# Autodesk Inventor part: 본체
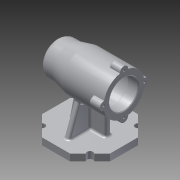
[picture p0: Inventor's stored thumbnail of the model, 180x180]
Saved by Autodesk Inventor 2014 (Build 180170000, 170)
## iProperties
Created: 2021-01
Part Number: 본체
Material: Aluminum 6061
Document SubType Name: Modeling
Designer: kh
Mass: 632.435 g
Surface Area: 613.582 cm^2
Volume: 233.371 cm^3
Density: 2.71 g/cm^3
Appearance: Aluminum - Flat
Author: kh
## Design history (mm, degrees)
sketch "Sketch1" dims "d0" = 100
  geometry: L1 (20.711, 50)-(50, 20.711); L2 (50, 20.711)-(50, -20.711); L3 (50, -20.711)-(20.711, -50); L4 (20.711, -50)-(-20.711, -50); L5 (-20.711, -50)-(-50, -20.711); L6 (-50, -20.711)-(-50, 20.711); L7 (-50, 20.711)-(-20.711, 50); L8 (-20.711, 50)-(20.711, 50); 4 further points
  constraints: 16 end point, 2 coincident, 2 vertical alignment, 1 midpoint, 19 other
extrude "Extrusion1" new body sketch "Sketch1" distance "d1" = 10; taper "d2" = 0 deg
sketch "Sketch2"
  geometry: L1 (50, 20.711)-(20.711, 50) reference; L2 (20.711, 50)-(-20.711, 50) reference; L3 (-20.711, 50)-(-50, 20.711) reference; L4 (-50, 20.711)-(-50, -20.711) reference; L5 (-50, -20.711)-(-20.711, -50) reference; L6 (-20.711, -50)-(20.711, -50) reference; L7 (20.711, -50)-(50, -20.711) reference; L8 (50, -20.711)-(50, 20.711) reference; L9 (-50, 0)-(50, 0); L10 (0, 50)-(0, -50); L11 (0, 0)-(-35.355, 35.355); C1 r 4.5 at (-35.355, 35.355); C2 r 4.5 at (-35.355, -35.355); C3 r 4.5 at (35.355, -35.355); C4 r 4.5 at (35.355, 35.355)
  constraints: 8 midpoint, 6 end point, 4 centre point, 1 coincident
  dimensions: "d3" = 9 diameter of C1; "d6" = 9 diameter of C2; "d7" = 9 diameter of C3; "d8" = 9 diameter of C4
  node "Projected Loop1"
extrude "Extrusion2" cut sketch "Sketch2" distance "d4" = 10; taper "d5" = 0 deg
extrude "Extrusion3" cut sketch "Sketch2" distance "d9" = 10; taper "d10" = 0 deg
sketch "Sketch3"
  geometry: L1 (20.711, 0)-(-20.711, 0) reference; L2 (-50, 0)-(-50, 10) reference; L3 (-50, 75)-(50, 75); L4 (50, 75)-(50, 100); L5 (50, 100)-(30, 100); L6 (30, 100)-(10, 105); L7 (10, 105)-(-50, 105); L8 (-50, 105)-(-50, 75); L9 (-50, 96)-(-35, 96); L10 (-35, 96)-(-35, 96); L11 (-32, 99)-(4, 99); L12 (7, 96)-(7, 96); L13 (7, 96)-(18.7, 96); L14 (19, 95.7)-(19, 92.5); L15 (19, 92.5)-(36.7, 92.5); L16 (37, 92.2)-(37, 91); L17 (37, 91)-(40.7, 91); L18 (41, 90.7)-(41, 85.5); L19 (41, 85.5)-(41, 85.5); L20 (44, 82.5)-(44, 75); A1 r 3 centre (41, 82.5) between (44, 82.5) and (41, 85.5); A2 r 0.3 centre (40.7, 90.7) between (41, 90.7) and (40.7, 91); A3 r 0.3 centre (36.7, 92.2) between (37, 92.2) and (36.7, 92.5); A4 r 0.3 centre (18.7, 95.7) between (19, 95.7) and (18.7, 96); A5 r 3 centre (4, 96) between (7, 96) and (4, 99); A6 r 3 centre (-32, 96) between (-32, 99) and (-35, 96); 3 further points
  constraints: 36 end point, 12 point on circle, 12 tangent, 10 parallel, 6 centre point, 6 perpendicular, 6 point on line, 3 equal radius, 2 collinear, 1 vertical alignment
  dimensions: "d11" = 100 distance of L3.start L3.end; "d12" = 75 distance from line of L2.start L3; "d13" = 60 diameter of L7 L3; "d14" = 50 diameter of L5 L3; "d15" = 20 distance from line of L5.end L4; "d16" = 40 distance from line of L6.end L4; "d17" = 42 diameter of L9 L3; "d18" = 48 diameter of L11 L3; "d19" = 35 diameter of L15 L3; "d20" = 32 diameter of L17 L3; "d21" = 21 diameter of L19 L3; "d22" = 15 distance between parallel lines of L8 L10; "d23" = 42 distance between parallel lines of L12 L10; "d24" = 12 distance between parallel lines of L12 L14; "d25" = 18 distance between parallel lines of L14 L16; "d26" = 4 distance between parallel lines of L16 L18; "d27" = 3 distance between parallel lines of L18 L20; "d28" = 3 radius of A1; "d29" = 0.3 radius of A2; "d31" = 3 radius of A5
revolve "Revolution1" sketch "Sketch3" stored, may be unused: angle "d30" = 90 deg
sketch "Sketch4"
  geometry: C1 r 6 at (-30, 0); 2 further points
  constraints: 2 horizontal alignment, 1 centre point, 1 other
  dimensions: "d32" = 12 diameter of C1
extrude "Extrusion4" join sketch "Sketch4" distance "d33" = 16; taper "d34" = 0 deg
pattern_circular "Circular Pattern1" dims angle "d36" = 360 deg
hole "Hole1" diameter "d40" = 3.242; stored, may be unused: countersink angle "d44" = 90 deg, drill point angle "d46" = 118 deg; dims "d38" = 10, "d39" = 10, "d41" = 8, "d42" = 4, "d43" = 2, "d45" = 10
pattern_circular "Circular Pattern2" dims angle "d48" = 360 deg
sketch "Sketch5"
  geometry: L1 (38.537, 10)-(50, 10) reference; L2 (30.855, 10)-(38.537, 10) reference; L3 (20.711, 10)-(32.173, 10) reference; L4 (-20.711, 10)-(20.711, 10) reference; L5 (-32.173, 10)-(-20.711, 10) reference; L6 (-38.537, 10)-(-30.855, 10) reference; L7 (-50, 10)-(-38.537, 10) reference; L8 (50, 0)-(38.537, 0) reference; L9 (38.537, 0)-(30.855, 0) reference; L10 (32.173, 0)-(20.711, 0) reference; L11 (20.711, 0)-(-20.711, 0) reference; L12 (-20.711, 0)-(-32.173, 0) reference; L13 (-30.855, 0)-(-38.537, 0) reference; L14 (-38.537, 0)-(-50, 0) reference; L15 (-34, 45)-(10, 45) reference; L16 (10, 45)-(30, 50) reference; L17 (27, 10)-(22.139, 35.006); L18 (-27, 10)-(-27, 35.006); L19 (27, 10)-(-27, 10); 1 further point
  constraints: 6 end point, 2 point on line, 1 collinear, 1 perpendicular
  dimensions: "d50" = 101 deg angle of L17 L3; "d51" = 23 distance of L1.end L17.start; "d52" = 23 distance from line of L7.start L18
feature "Rib1" sketch "Sketch5" dims "d53" = 1, "d54" = 8, "d55" = 0, "d56" = 0, "d57" = 1, "d58" = 1
sketch "Sketch6"
  geometry: L1 (20.711, 10)-(-20.711, 10) reference; L2 (-20.711, 10)-(-32.173, 10) reference; L3 (-38.537, 10)-(-30.855, 10) reference; L4 (-38.537, 10)-(-50, 10) reference; L5 (32.173, 10)-(20.711, 10) reference; L6 (30.855, 10)-(38.537, 10) reference; L7 (50, 10)-(38.537, 10) reference; L8 (-35, 10)-(-19.606, 52.293); L9 (35, 10)-(19.606, 52.293); L10 (-35, 10)-(35, 10); C1 r 1.621 at (-30, 75) reference; C2 r 1.621 at (0, 45) reference; C3 r 1.621 at (30, 75) reference; C4 r 1.621 at (0, 105) reference; C5 r 21 at (0, 75) reference; A1 r 30 centre (0, 75) between (-29.4, 69.03) and (-5.97, 45.6) reference; A2 r 6 centre (0, 45) between (-5.97, 45.6) and (5.97, 45.6) reference; A3 r 30 centre (0, 75) between (5.97, 45.6) and (29.4, 69.03) reference; A4 r 6 centre (30, 75) between (29.4, 69.03) and (29.4, 80.97) reference; A5 r 30 centre (0, 75) between (29.4, 80.97) and (5.97, 104.4) reference; A6 r 6 centre (0, 105) between (5.97, 104.4) and (-5.97, 104.4) reference; A7 r 30 centre (0, 75) between (-5.97, 104.4) and (-29.4, 80.97) reference; A8 r 6 centre (-30, 75) between (-29.4, 80.97) and (-29.4, 69.03) reference; A9 r 30 centre (0, 75) between (-19.606, 52.293) and (19.606, 52.293); 1 further point
  constraints: 6 end point, 5 point on circle, 2 point on line, 1 centre point, 1 collinear
  dimensions: "d59" = 15 distance of L8.start L4.end; "d60" = 15 distance of L7.start L9.start; "d61" = 110 deg angle of L7 L9; "d62" = 110 deg angle of L4 L8
extrude "Extrusion5" join sketch "Sketch6" stored distance "d63" = 8; taper "d64" = 0 deg
fillet "Fillet1" dims "d65" = 10
fillet "Fillet2" dims "d66" = 3
fillet "Fillet3" dims "d67" = 1
fillet "Fillet6" dims "d70" = 3
fillet "Fillet8" dims "d72" = 3
fillet "Fillet9" dims "d73" = 3
chamfer "Chamfer1" distance "d74" = 1; stored, may be unused: second distance "d75" = 2, angle "d76" = 45 deg
body "Solid1"
node "Projected Loop2"
